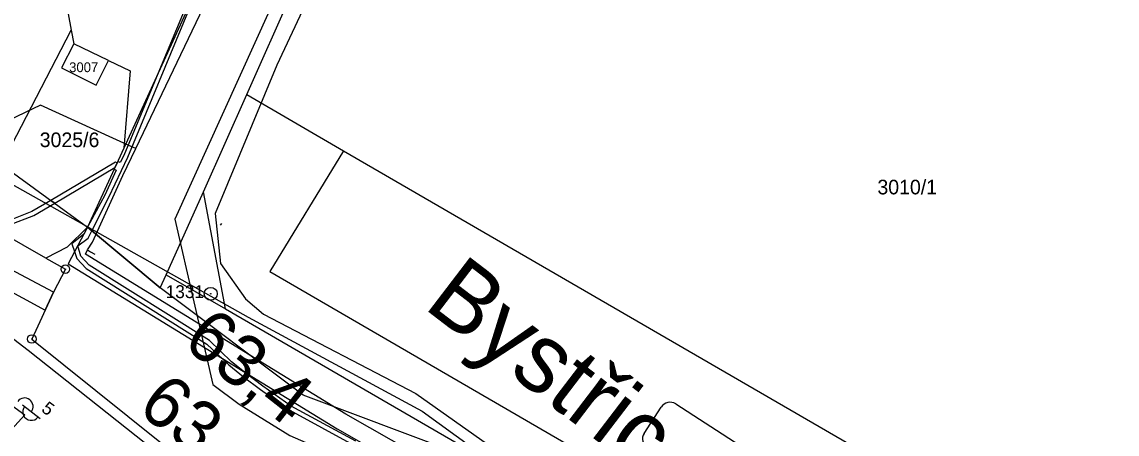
# Model space of a CAD drawing. Extents: x -620475 to -619963, y -1123010 to -1122510.
# Drawn here: x -620299.9 to -620172.3, y -1122665.8 to -1122617.9 of the extents above; entities that cross this region are included whole.
import ezdxf

# ---------------------------------------------------------------- set-up
doc = ezdxf.new("R2010")
doc.units = 0
for name, color, linetype in [('bubliny', 7, 'Continuous'), ('CETIN', 7, 'Continuous'), ('GasNet', 7, 'Continuous'), ('HranDP', 7, 'Continuous'), ('Hranice parcel', 7, 'Continuous'), ('Parcelní čísla', 7, 'Continuous'), ('VAS vodovod', 7, 'Continuous'), ('Vnitřní kresba', 7, 'Continuous'), ('Vrstva 23', 7, 'Continuous'), ('Vrstva 25', 7, 'Continuous'), ('Vrstva 7', 7, 'Continuous'), ('Věcná břemena k části', 7, 'Continuous'), ('Značky bodu BP', 7, 'Continuous')]:
    doc.layers.add(name, color=color, linetype=linetype)

msp = doc.modelspace()

# ---------------------------------------------------------------- linework, layer by layer
at = {"layer": 'bubliny'}
for points in [[(-620227.38, -1122665.75), (-620225.4, -1122662.68)], [(-620223.71, -1122662.32), (-620205.28, -1122674.22)]]:
    msp.add_lwpolyline(points, dxfattribs=at)
for centre, start, end in [((-620224.37, -1122663.34), 57.141, 147.141), ((-620226.36, -1122666.41), 147.141, 237.141)]:
    msp.add_arc(centre, 1.22, start, end, dxfattribs=at)
at = {"layer": 'CETIN'}
for points in [[(-620235.57, -1122548.13), (-620243.46, -1122564.23), (-620245.21, -1122568), (-620248.13, -1122575.41), (-620249.64, -1122579.23), (-620250.03, -1122580.22), (-620259.73, -1122600.63), (-620270.17, -1122622.89), (-620277.38, -1122640.15)], [(-620322.39, -1122622.26), (-620301.06, -1122636.75), (-620273.54, -1122652.22), (-620253.25, -1122663.16), (-620204.02, -1122698.84), (-620159.64, -1122769.19), (-620144.67, -1122791.29), (-620140.33, -1122798.33), (-620134.98, -1122805.25), (-620121.23, -1122817.18), (-620095.95, -1122832.42), (-620068, -1122848.18)], [(-620277.38, -1122640.15), (-620276.74, -1122645.99), (-620273.83, -1122650.1), (-620271.73, -1122651.88), (-620253.98, -1122661.12), (-620237.57, -1122672.68), (-620221.58, -1122684.68), (-620204.03, -1122697.14), (-620190.46, -1122716.45), (-620176.22, -1122740.39), (-620170.94, -1122748.28)]]:
    msp.add_lwpolyline(points, dxfattribs=at)
at = {"layer": 'GasNet'}
msp.add_lwpolyline([(-620239.81, -1122544.41), (-620244.84, -1122557.48), (-620248.53, -1122566.67), (-620254.12, -1122579.23), (-620282.06, -1122640.8), (-620277.64, -1122660.05), (-620274.59, -1122662.36), (-620268.66, -1122665.97), (-620260.67, -1122669.48), (-620248.93, -1122674.43), (-620234.6, -1122684.05), (-620224.06, -1122692.21), (-620218.44, -1122696.68), (-620207.68, -1122707.92), (-620198.08, -1122719.79), (-620190.17, -1122731.16), (-620189.77, -1122731.74), (-620188.17, -1122734.04)], dxfattribs=at)
at = {"layer": 'HranDP'}
for points in [[(-620297.09, -1122645.35), (-620318.55, -1122633.1), (-620335.09, -1122623.49), (-620335.54, -1122621.75)], [(-620297.09, -1122645.35), (-620294.83, -1122646.64), (-620296.23, -1122649.3)], [(-620296.23, -1122649.3), (-620298.73, -1122654.76), (-620265, -1122681.82), (-620263.22, -1122682.69), (-620260.55, -1122682.94), (-620253.83, -1122686.12), (-620245.73, -1122689.53), (-620242.51, -1122691.82), (-620225.75, -1122705.35), (-620226.24, -1122705.93)]]:
    msp.add_lwpolyline(points, dxfattribs=at)
at = {"layer": 'Hranice parcel'}
for p, q in [((-620272.42, -1122598.5), (-620288.03, -1122632.56)), ((-620295.2, -1122613.12), (-620294.15, -1122618.83)), ((-620302.25, -1122634.43), (-620294.15, -1122618.83)), ((-620294.15, -1122618.83), (-620293.86, -1122620.43)), ((-620289.81, -1122622.36), (-620293.86, -1122620.43)), ((-620273.7, -1122626.32), (-620262.42, -1122632.85)), ((-620288.03, -1122632.56), (-620292.25, -1122641.75)), ((-620292.25, -1122641.75), (-620283.77, -1122648.8))]:
    msp.add_line(p, q, dxfattribs=at)
for points in [[(-620273.7, -1122626.32), (-620263.06, -1122602.36), (-620252.8, -1122580.02)], [(-620296.23, -1122649.3), (-620347.83, -1122621.96), (-620355.23, -1122633.54), (-620375.94, -1122620.82)], [(-620293.86, -1122620.43), (-620295.29, -1122623.2), (-620291.25, -1122625.22), (-620289.81, -1122622.36)], [(-620297.09, -1122645.35), (-620318.55, -1122633.1), (-620335.09, -1122623.49), (-620335.54, -1122621.75)], [(-620289.81, -1122622.36), (-620287.29, -1122623.55), (-620288.03, -1122632.56)], [(-620283.77, -1122648.8), (-620283.08, -1122647.29), (-620278.72, -1122637.63), (-620273.7, -1122626.32)], [(-620262.42, -1122632.85), (-620271, -1122646.92), (-620195.53, -1122690.65), (-620197.92, -1122694.75), (-620198.58, -1122696.08), (-620199.01, -1122697.5), (-620199.13, -1122698.99), (-620198.88, -1122700.47), (-620198.25, -1122701.83), (-620197.37, -1122703.03), (-620195.84, -1122704.31), (-620190.67, -1122707.32), (-620190.09, -1122707.94), (-620189.82, -1122708.78), (-620189.94, -1122709.65), (-620191.6, -1122712.59), (-620176.88, -1122721.09), (-620165.63, -1122727.6)], [(-620262.42, -1122632.85), (-620187.21, -1122676.39), (-620163.01, -1122690.49), (-620140.63, -1122703.48)], [(-620302.25, -1122634.43), (-620301.71, -1122634.83), (-620292.25, -1122641.75)], [(-620292.25, -1122641.75), (-620294.63, -1122644.08), (-620297.09, -1122645.35)], [(-620297.09, -1122645.35), (-620294.83, -1122646.64), (-620296.23, -1122649.3)], [(-620296.23, -1122649.3), (-620298.73, -1122654.76), (-620265, -1122681.82), (-620263.22, -1122682.69), (-620260.55, -1122682.94), (-620253.83, -1122686.12), (-620245.73, -1122689.53), (-620242.51, -1122691.82), (-620225.75, -1122705.35), (-620226.24, -1122705.93)], [(-620186.47, -1122727.64), (-620202.54, -1122702), (-620243.36, -1122670.23), (-620267.12, -1122661.31), (-620283.77, -1122648.8)], [(-620302.66, -1122666.96), (-620267.81, -1122694.49), (-620266.86, -1122693.31), (-620261.82, -1122686.93), (-620261.22, -1122686.17), (-620299.15, -1122656.1), (-620301.83, -1122654.06), (-620305.28, -1122659.46), (-620299.56, -1122663.58), (-620302.66, -1122666.96)]]:
    msp.add_lwpolyline(points, dxfattribs=at)
at = {"layer": 'VAS vodovod'}
msp.add_line((-620276.65, -1122641.33), (-620276.79, -1122641.51), dxfattribs=at)
for points in [[(-620187.76, -1122731.9), (-620195.94, -1122716.94), (-620196.8, -1122715.72), (-620204.13, -1122705.27), (-620209.09, -1122701.32), (-620227.02, -1122686.32), (-620229.71, -1122684.31), (-620243.1, -1122674.33), (-620262.14, -1122663.5), (-620292.5, -1122644.88), (-620292.27, -1122644.4), (-620291.67, -1122643.5), (-620288.12, -1122635.73), (-620286.62, -1122632.6), (-620277.43, -1122613.36), (-620264.89, -1122587.07), (-620260.25, -1122576.44), (-620256.1, -1122566.95), (-620252.51, -1122559.26)], [(-620286.62, -1122632.6), (-620287.08, -1122632.39), (-620297.74, -1122627.56), (-620305.96, -1122631.45), (-620337.21, -1122616.49), (-620336.27, -1122613.97)], [(-620292.27, -1122644.4), (-620291.92, -1122644.63), (-620291.4, -1122644.89)]]:
    msp.add_lwpolyline(points, dxfattribs=at)
at = {"layer": 'Vnitřní kresba'}
for p, q in [((-620276.18, -1122651.26), (-620278.72, -1122637.63)), ((-620283.08, -1122647.29), (-620276.18, -1122651.26)), ((-620276.18, -1122651.26), (-620243.36, -1122670.23))]:
    msp.add_line(p, q, dxfattribs=at)
at = {"layer": 'Vrstva 25'}
msp.add_line((-620299.83, -1122662.43), (-620297.76, -1122664), dxfattribs=at)
for centre, start, end in [((-620299.59, -1122662.62), 322.8473, 142.8473), ((-620298.8, -1122663.23), 142.1447, 323.5498)]:
    msp.add_arc(centre, 1, start, end, dxfattribs=at)
at = {"layer": 'Věcná břemena k části'}
for points in [[(-620280.81, -1122616.1), (-620284.07, -1122623.91), (-620288.03, -1122633.42), (-620288.46, -1122634.22), (-620288.73, -1122634.09), (-620289.15, -1122634.99), (-620288.92, -1122635.1), (-620290.22, -1122638.02), (-620292.25, -1122641.75), (-620291.74, -1122642.18), (-620289.78, -1122638.24), (-620287.57, -1122633.62), (-620280.35, -1122616.3)], [(-620301.34, -1122641.49), (-620298.51, -1122640.4), (-620296.07, -1122638.96), (-620296.51, -1122638.63), (-620298.73, -1122639.94), (-620301.26, -1122640.93)], [(-620260.98, -1122666.66), (-620268.51, -1122662.58), (-620271.81, -1122660.24), (-620273.76, -1122658.77), (-620275.47, -1122657.4), (-620278.05, -1122654.95), (-620292.07, -1122646.16), (-620293.04, -1122645.12), (-620293.38, -1122643.9), (-620292.16, -1122643.03), (-620291.74, -1122642.18), (-620292.25, -1122641.75), (-620292.68, -1122642.57), (-620294.09, -1122643.68), (-620293.75, -1122644.59), (-620293.48, -1122645.38), (-620292.39, -1122646.54), (-620278.35, -1122655.35), (-620275.79, -1122657.78), (-620274.06, -1122659.17), (-620272.11, -1122660.64), (-620268.77, -1122663), (-620261.22, -1122667.1)]]:
    msp.add_lwpolyline(points, dxfattribs=at)
for points in [[(-620297.19, -1122651.39), (-620296.23, -1122649.3), (-620347.83, -1122621.96), (-620348.75, -1122623.39)], [(-620296.07, -1122638.96), (-620289.07, -1122634.82), (-620288.81, -1122634.26), (-620288.99, -1122634.19), (-620296.51, -1122638.63)], [(-620283.77, -1122648.8), (-620292.25, -1122641.75), (-620294.49, -1122646), (-620263.15, -1122665.23), (-620244.2, -1122676.01), (-620228.26, -1122687.89), (-620210.35, -1122702.87), (-620205.6, -1122706.65), (-620197.64, -1122718), (-620190.71, -1122730.68), (-620186.47, -1122727.64), (-620202.54, -1122702), (-620243.36, -1122670.23), (-620267.12, -1122661.31)]]:
    msp.add_lwpolyline(points, close=True, dxfattribs=at)
at = {"layer": 'Značky bodu BP'}
for centre, radius in [((-620294.83, -1122646.64), 0.5), ((-620294.83, -1122646.64), 0.0303), ((-620277.89, -1122649.5), 0.75), ((-620277.89, -1122649.5), 0.03), ((-620298.73, -1122654.76), 0.5), ((-620298.73, -1122654.76), 0.0303)]:
    msp.add_circle(centre, radius, dxfattribs=at)

# ---------------------------------------------------------------- texts
at = {"layer": 'Parcelní čísla'}
for s, height, p in [('3007', 1.139, (-620294.39, -1122623.71)), ('3025/6', 1.7, (-620297.82, -1122632.43)), ('3010/1', 1.7, (-620200.21, -1122637.93))]:
    msp.add_text(s, height=height, dxfattribs=at).set_placement(p)
at = {"layer": 'Vrstva 23'}
msp.add_text('Bystřice nad Pernštejnem', height=8, rotation=322.5799, dxfattribs=at).set_placement((-620253.24, -1122651.06))
at = {"layer": 'Vrstva 25'}
msp.add_text('5', height=1.5, rotation=322.8473, dxfattribs=at).set_placement((-620297.73, -1122663.1))
at = {"layer": 'Vrstva 7'}
for p in [(-620281.34, -1122655.45), (-620286.61, -1122663.08)]:
    msp.add_text('63,4', height=6, rotation=321.8255, dxfattribs=at).set_placement(p)
at = {"layer": 'Značky bodu BP'}
msp.add_text('1331', height=1.5, dxfattribs=at).set_placement((-620283.14, -1122650))

doc.saveas('drawing.dxf')
